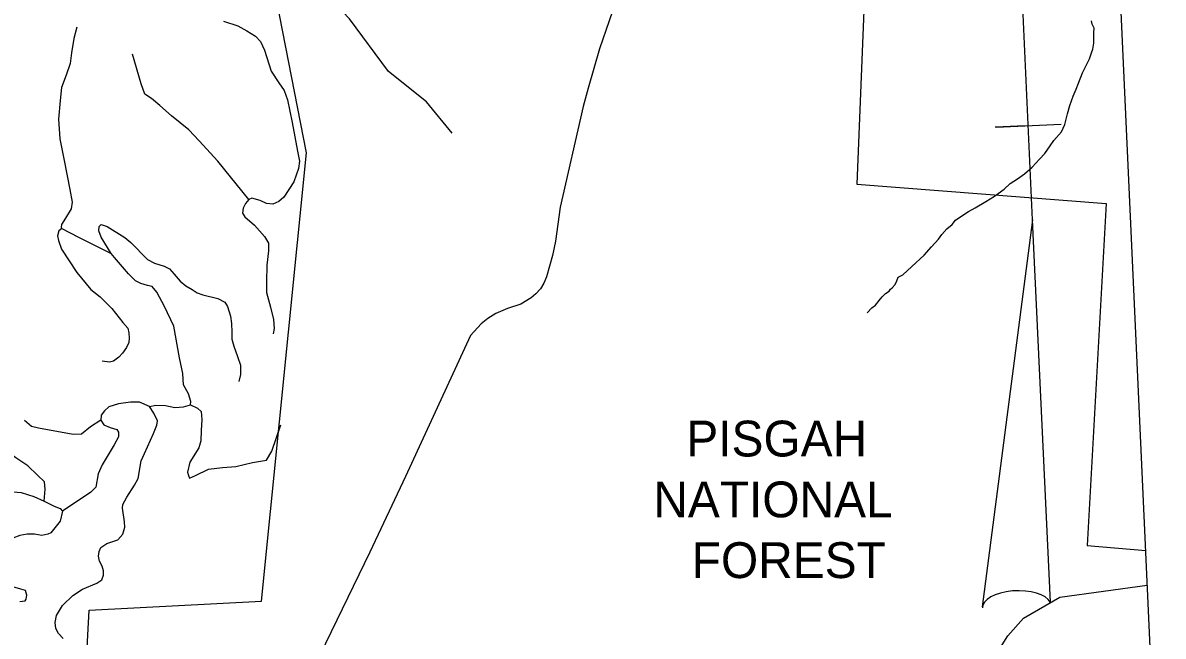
# Model space of a CAD drawing. Extents: x 1190067 to 1192950, y 891516 to 893460.
# Drawn here: x 1191052.1 to 1191171.9, y 893115.8 to 893180.3 of the extents above; entities that cross this region are included whole.
import ezdxf

# ---------------------------------------------------------------- set-up
doc = ezdxf.new("R2010")
doc.units = 0
for name, color, linetype in [('Default', 7, 'Continuous'), ('Prop DSN Text', 7, 'Continuous'), ('Prop North Arrow for Plan Sheets CELL', 7, 'Continuous')]:
    doc.layers.add(name, color=color, linetype=linetype)

msp = doc.modelspace()

# ---------------------------------------------------------------- linework, layer by layer
at = {"layer": 'Default'}
for points in [[(1191097.18, 893168.68), (1191094.5, 893171.95), (1191090.49, 893175.14), (1191086.42, 893180.67), (1191081.03, 893186.36), (1191077, 893194.48), (1191078.3, 893198.53), (1191080.43, 893202.39), (1191080.78, 893204.28), (1191081.2, 893214.38), (1191081.81, 893215.81), (1191085.75, 893220.67), (1191086.4, 893222.96), (1191085.96, 893228.36), (1191086.57, 893240.36), (1191084.14, 893247.42), (1191082.2, 893256.65), (1191081.92, 893262.8), (1191082.57, 893265.26), (1191083.65, 893267.13), (1191088.46, 893272.83), (1191088.66, 893274.15)], [(1191097.18, 893168.68), (1191094.5, 893171.95), (1191090.49, 893175.14), (1191086.42, 893180.67), (1191081.03, 893186.36), (1191077, 893194.48), (1191078.3, 893198.53), (1191080.43, 893202.39), (1191080.78, 893204.28), (1191081.2, 893214.38), (1191081.81, 893215.81), (1191085.75, 893220.67), (1191086.4, 893222.96), (1191085.96, 893228.36), (1191086.57, 893240.36), (1191084.14, 893247.42), (1191082.2, 893256.65), (1191081.92, 893262.8), (1191082.57, 893265.26), (1191083.65, 893267.13), (1191088.46, 893272.83), (1191088.66, 893274.15)], [(1191029.27, 893078.13), (1191029.98, 893090.66), (1191057.48, 893089.03), (1191059.04, 893118.58), (1191077.17, 893119.53), (1191081.87, 893166.61), (1191078.77, 893182.53), (1191096.87, 893187.19), (1191140.63, 893185.93), (1191139.74, 893163.32), (1191165.93, 893161.29), (1191163.96, 893125.35), (1191170.1, 893124.83)], [(1191114.73, 893183.43), (1191112.7, 893177.54), (1191111.48, 893173.39), (1191110.97, 893171.48), (1191108.56, 893160.9), (1191108.07, 893157.32), (1191107.75, 893155.82), (1191107.1, 893153.58), (1191106.82, 893152.92), (1191106.49, 893152.33), (1191106, 893151.78), (1191105.49, 893151.36), (1191104.43, 893150.71), (1191103.03, 893150.25), (1191101.77, 893149.71), (1191100.94, 893149.19), (1191100.26, 893148.63), (1191099.14, 893147.43), (1191092.3, 893132.61), (1191088.54, 893124.67), (1191080.43, 893107.91)], [(1191057.73, 893179.81), (1191057.43, 893178.61), (1191057.17, 893177.09), (1191057.03, 893175.99), (1191056.61, 893174.77), (1191056.12, 893173.46), (1191055.98, 893172.08), (1191055.83, 893170.14), (1191055.97, 893168.08), (1191056.41, 893165.78), (1191057.01, 893162.76), (1191057.26, 893161.43), (1191057.15, 893160.73), (1191056.54, 893159.74), (1191056.12, 893159.06), (1191056.11, 893158.81), (1191056.18, 893158.64)], [(1191073.15, 893180.42), (1191074.67, 893179.93), (1191075.61, 893179.43), (1191076.54, 893178.87), (1191077.06, 893178.29), (1191077.46, 893177.37), (1191078.16, 893175.17), (1191078.97, 893173.96), (1191079.53, 893173.14), (1191079.88, 893172.15), (1191080.37, 893169.79), (1191080.94, 893166.77), (1191081.15, 893165.74), (1191081.06, 893164.94), (1191080.55, 893163.56), (1191079.5, 893161.94), (1191078.99, 893161.5), (1191078.36, 893161.22), (1191077.68, 893161.27), (1191077.02, 893161.59), (1191076.13, 893161.83), (1191075.83, 893161.71)], [(1191140.82, 893149.8), (1191141.32, 893150.31), (1191141.68, 893150.61), (1191142.08, 893151.09), (1191142.4, 893151.47), (1191142.76, 893151.81), (1191143.12, 893152.08), (1191143.27, 893152.29), (1191143.44, 893152.42), (1191143.77, 893152.77), (1191143.95, 893153.14), (1191144.07, 893153.53), (1191144.57, 893153.79), (1191145.5, 893154.68), (1191146.8, 893155.87), (1191147.59, 893156.73), (1191148.31, 893157.55), (1191148.67, 893158.03), (1191149.18, 893158.61), (1191149.75, 893159.08), (1191150.12, 893159.53), (1191150.76, 893159.97), (1191151.47, 893160.44), (1191152.18, 893160.84), (1191153.29, 893161.48), (1191154.21, 893162.04), (1191155.21, 893162.79), (1191155.86, 893163.37), (1191156.61, 893163.87), (1191157.36, 893164.41), (1191158.18, 893165.09), (1191158.94, 893165.94), (1191159.48, 893166.53), (1191160.07, 893167.35), (1191160.43, 893167.9), (1191161.26, 893168.79), (1191161.6, 893169.59), (1191161.87, 893170.7), (1191162.14, 893171.57), (1191162.48, 893172.54), (1191162.78, 893173.3), (1191163.04, 893173.92), (1191163.46, 893175), (1191163.79, 893175.72), (1191164.2, 893176.48), (1191164.39, 893177.11), (1191164.54, 893177.49), (1191164.63, 893178.12), (1191164.65, 893178.75), (1191164.66, 893179.24), (1191164.67, 893179.69), (1191164.47, 893180.12), (1191164.41, 893180.47)], [(1191075.83, 893161.71), (1191072.55, 893165.74), (1191070.61, 893167.87), (1191069.51, 893169.02), (1191068.61, 893169.74), (1191067.68, 893170.49), (1191066.48, 893171.57), (1191065.59, 893172.29), (1191064.89, 893172.76), (1191064.49, 893173.84), (1191063.59, 893176.95)], [(1191075.83, 893161.71), (1191075.47, 893161.29), (1191075.21, 893160.8), (1191075.16, 893160.26), (1191075.42, 893159.88), (1191076.43, 893159.02), (1191077.46, 893157.82), (1191077.9, 893157.1), (1191077.9, 893156.3), (1191077.71, 893154.8), (1191077.67, 893153.05), (1191077.67, 893151.92), (1191078.1, 893150.4), (1191078.4, 893149.11), (1191078.5, 893148.15), (1191078.38, 893147.59)], [(1191061.35, 893156.02), (1191060.29, 893157.75), (1191060.06, 893158.41), (1191060.08, 893158.85), (1191060.29, 893159.09), (1191060.93, 893158.88), (1191062.8, 893157.71), (1191063.43, 893157.17), (1191065.16, 893155.39), (1191065.91, 893155.01), (1191066.94, 893154.71), (1191067.47, 893154.43), (1191067.96, 893153.84), (1191068.59, 893153.12), (1191069.2, 893152.63), (1191069.88, 893152.23), (1191070.39, 893151.9), (1191071, 893151.69), (1191072.57, 893151.31), (1191073.29, 893150.92), (1191073.57, 893150.45), (1191073.88, 893149.46), (1191074.01, 893148.67), (1191074.03, 893147.76), (1191074.03, 893147.03), (1191074.26, 893146.3), (1191074.64, 893145.2), (1191074.94, 893144.31), (1191074.94, 893143.33), (1191074.77, 893142.58)], [(1191056.18, 893158.64), (1191055.86, 893158.41), (1191055.72, 893157.87), (1191055.81, 893157.4), (1191056.12, 893156.47), (1191057.73, 893154.03), (1191059.23, 893152.23), (1191060.19, 893151.48), (1191061.41, 893150.26), (1191062.59, 893148.79), (1191063.1, 893148.18), (1191063.22, 893147.71), (1191063.24, 893147.15), (1191063.2, 893146.68), (1191062.96, 893146.14), (1191062.56, 893145.55), (1191062.17, 893145.13), (1191061.6, 893144.71), (1191061.18, 893144.62), (1191060.41, 893144.71)], [(1191056.18, 893158.64), (1191057.93, 893157.73), (1191061.35, 893156.02)], [(1191069.69, 893140.12), (1191069.74, 893140.5), (1191069.48, 893141.29), (1191068.96, 893142.23), (1191068.87, 893143.42), (1191068.54, 893145.06), (1191067.93, 893148.41), (1191066.96, 893150.47), (1191066.14, 893151.95), (1191065.65, 893152.56), (1191065.16, 893152.67), (1191064.46, 893152.86), (1191063.92, 893153.16), (1191063.17, 893153.89), (1191061.7, 893155.6), (1191061.35, 893156.02)], [(1191056.31, 893115.59), (1191055.81, 893116.13), (1191055.54, 893116.66), (1191055.46, 893117.28), (1191055.62, 893118.01), (1191056.23, 893119.05), (1191057.31, 893120.12), (1191058.34, 893120.78), (1191059.86, 893121.39), (1191060.36, 893121.77), (1191060.55, 893122.24), (1191060.55, 893122.7), (1191060.4, 893123.2), (1191060.13, 893123.73), (1191060.01, 893124.23), (1191060.09, 893124.73), (1191060.28, 893125.16), (1191060.9, 893125.58), (1191062.05, 893125.96), (1191062.59, 893126.54), (1191062.78, 893127.27), (1191062.74, 893127.85), (1191062.55, 893129.27), (1191062.59, 893129.65), (1191063.01, 893130.42), (1191063.81, 893131.69), (1191064.18, 893132.38), (1191064.52, 893134.26), (1191064.87, 893135.03), (1191065.79, 893137.14), (1191066.14, 893137.99), (1191066.21, 893138.45), (1191065.83, 893139.26), (1191065.37, 893139.95)], [(1191065.37, 893139.95), (1191064.33, 893140.41), (1191063.37, 893140.41), (1191062.14, 893140.25), (1191061.11, 893139.91), (1191060.65, 893139.49), (1191060.3, 893139.06), (1191060.26, 893138.53)], [(1191065.37, 893139.95), (1191066.06, 893140.1), (1191067.06, 893140.06), (1191068.06, 893139.87), (1191068.94, 893139.91), (1191069.69, 893140.12), (1191070.44, 893139.79), (1191070.82, 893139.45), (1191070.9, 893138.6), (1191070.82, 893137.45), (1191070.78, 893136.37), (1191070.55, 893135.61), (1191069.63, 893134.11), (1191069.36, 893133.07), (1191069.48, 893132.72), (1191069.59, 893132.42), (1191070.21, 893132.72), (1191071.59, 893133.38), (1191073.05, 893133.57), (1191074.47, 893133.65), (1191076.2, 893134.07), (1191077.69, 893134.34), (1191078.23, 893135.26), (1191079.19, 893138.03)], [(1191060.26, 893138.53), (1191059.19, 893137.83), (1191058.23, 893137.07), (1191057.35, 893137.03), (1191053.7, 893137.68), (1191052.97, 893137.87), (1191052.24, 893138.49)], [(1191060.26, 893138.53), (1191060.57, 893138.03), (1191061.26, 893137.76), (1191061.95, 893137.53), (1191062.11, 893137.26), (1191062.11, 893136.76), (1191061.65, 893135.95), (1191060.42, 893133.84), (1191059.99, 893132.88), (1191059.73, 893131.5), (1191059.23, 893130.96), (1191056.23, 893128.96)], [(1191054.31, 893130), (1191054.43, 893131.26), (1191054.35, 893132.03), (1191053.62, 893132.76), (1191052.58, 893133.72), (1191051.32, 893134.57), (1191050.47, 893135.22), (1191049.97, 893135.38), (1191049.44, 893135.49)], [(1191045.75, 893130.46), (1191046.94, 893130.53), (1191048.17, 893130.84), (1191049.63, 893131.03), (1191050.63, 893131.03), (1191051.89, 893130.92), (1191053.24, 893130.5), (1191054.31, 893130), (1191055.35, 893129.5), (1191056, 893129.23), (1191056.23, 893128.96)], [(1191056.23, 893128.96), (1191056, 893127.92), (1191055, 893126.69), (1191054.7, 893126.54), (1191054.08, 893126.42), (1191053.28, 893126.54), (1191052.51, 893126.54), (1191051.74, 893126.42), (1191051.01, 893126.12), (1191050.55, 893125.77), (1191050.28, 893124.96), (1191050.09, 893123.47)], [(1191051.76, 893119.47), (1191052.3, 893119.55), (1191052.41, 893119.74), (1191052.49, 893120.16), (1191052.33, 893120.62), (1191051.84, 893120.78), (1191051.03, 893121.01), (1191050.38, 893121.28), (1191050.07, 893121.85), (1191050.03, 893122.62), (1191050.09, 893123.47)], [(1191085.93, 893081.99), (1191098.18, 893091.91), (1191108.97, 893097.44), (1191116.78, 893100.16), (1191120.6, 893100.66), (1191124.08, 893100.24), (1191138.39, 893100.87), (1191141.79, 893101.96), (1191146.53, 893104.62), (1191150.4, 893107.59), (1191155.59, 893115.87), (1191157.24, 893117.73), (1191161.09, 893119.95), (1191170.27, 893121.19)]]:
    msp.add_lwpolyline(points, dxfattribs=at)
at = {"layer": 'Prop DSN Text'}
msp.add_line((1191171.94, 893084.66), (1191159.03, 893366.78), dxfattribs=at)
msp.add_line((1191171.94, 893084.66), (1191159.03, 893366.78), dxfattribs=at)
msp.add_line((1191171.94, 893084.66), (1191159.03, 893366.78), dxfattribs=at)
at = {"layer": 'Prop North Arrow for Plan Sheets CELL'}
for p, q in [((1191158.2, 893159.55), (1191157.18, 893181.89)), ((1191154.34, 893169.28), (1191154.29, 893169.28)), ((1191157.36, 893169.42), (1191154.34, 893169.28)), ((1191154.38, 893169.29), (1191161.2, 893169.6)), ((1191158.2, 893159.55), (1191152.92, 893118.92)), ((1191160.08, 893119.42), (1191158.2, 893159.55))]:
    msp.add_line(p, q, dxfattribs=at)
msp.add_ellipse((1191156.54, 893118.94), major_axis=(3.61, 0.14), ratio=0.461098, start_param=0.201328, end_param=3.141593, dxfattribs=at)

# ---------------------------------------------------------------- texts
at = {"layer": 'Default'}
for s, p in [('PISGAH ', (1191121.81, 893134.71)), ('NATIONAL ', (1191118.34, 893128.32)), ('FOREST', (1191122.38, 893121.94))]:
    msp.add_text(s, height=3.762, dxfattribs=at).set_placement(p)

doc.saveas('drawing.dxf')
